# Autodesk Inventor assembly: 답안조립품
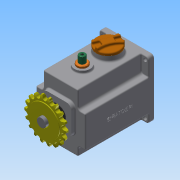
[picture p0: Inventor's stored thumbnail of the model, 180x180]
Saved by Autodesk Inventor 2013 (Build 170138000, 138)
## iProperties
Created: 2017-12
Part Number: 답안조립품
Document SubType Name: Assembly
Designer: Administrator
Mass: 2641.93 g
Surface Area: 2015.55 cm^2
Volume: 734.129 cm^3
Density: 3.59873 g/cm^3
Author: Administrator
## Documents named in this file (17)
- C:\Users\Administrator\Desktop\371208V1014\답안조립품.iam
- C:\Users\Administrator\Desktop\371208V1014\본체.ipt
- C:\Users\Administrator\Desktop\371208V1014\가변스프링.ipt
- C:\Users\Administrator\Desktop\371208V1014\멈춤나사 M3x8.ipt
- C:\Users\Administrator\Desktop\371208V1014\메인축.ipt
- C:\Users\Administrator\Desktop\371208V1014\베어링 608.ipt
- C:\Users\Administrator\Desktop\371208V1014\베어링 6003.ipt
- C:\Users\Administrator\Desktop\371208V1014\볼트 M4 x 10.ipt
- C:\Users\Administrator\Desktop\371208V1014\부시.ipt
- C:\Users\Administrator\Desktop\371208V1014\상부 캡.ipt
- C:\Users\Administrator\Desktop\371208V1014\서브축.ipt
- C:\Users\Administrator\Desktop\371208V1014\스프로킷.ipt
- C:\Users\Administrator\Desktop\371208V1014\슬라이더.ipt
- C:\Users\Administrator\Desktop\371208V1014\오일 실 8 22 7.ipt
- C:\Users\Administrator\Desktop\371208V1014\오일 실 17 32 8.ipt
- C:\Users\Administrator\Desktop\371208V1014\커버.ipt
- C:\Users\Administrator\Desktop\371208V1014\키 5 x 5 x 18.ipt
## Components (1 placed, 1 different names)
1. 가변스프링:1
